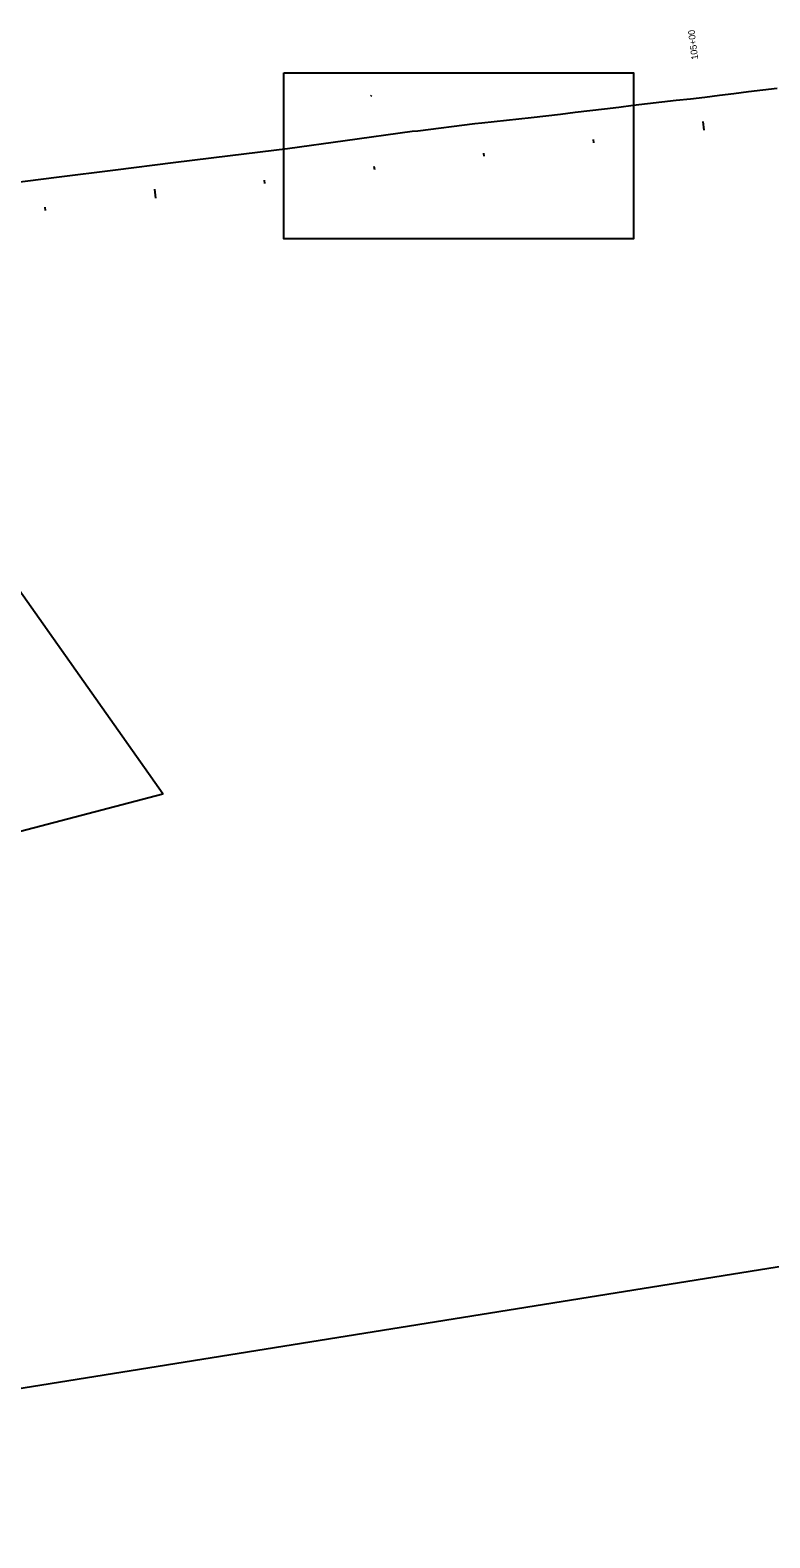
# Model space of a CAD drawing. Extents: x 1568908 to 1572777, y 730965 to 733090.
# Drawn here: x 1570174 to 1570843, y 730965 to 732330 of the extents above; entities that cross this region are included whole.
import ezdxf

# ---------------------------------------------------------------- set-up
doc = ezdxf.new("R2010")
doc.units = 0
for name, color, linetype in [('R_Erosion', 7, 'Continuous'), ('R_Horz Alg Annot', 7, 'Continuous'), ('R_No Plot', 7, 'Continuous')]:
    doc.layers.add(name, color=color, linetype=linetype)

msp = doc.modelspace()

# ---------------------------------------------------------------- linework, layer by layer
at = {"layer": 'R_Erosion'}
msp.add_line((1570481.8, 732270.6), (1570482.3, 732271.4), dxfattribs=at)
at = {"layer": 'R_Horz Alg Annot'}
for points in [[(1570782.1, 732247.6), (1570783.1, 732239.7)], [(1570683.7, 732228.4), (1570683.4, 732231.4)], [(1570584.5, 732216.1), (1570584.1, 732219.1)], [(1570485.3, 732203.9), (1570484.9, 732206.8)], [(1570285.9, 732186.3), (1570286.9, 732178.3)], [(1570386, 732191.6), (1570385.6, 732194.6)], [(1570187.5, 732167), (1570187.2, 732170)]]:
    msp.add_lwpolyline(points, dxfattribs=at)
at = {"layer": 'R_No Plot'}
for p, q in [((1570575.9, 732245.5), (1570524.3, 732238.8)), ((1570575.9, 732245.5), (1570524.3, 732238.8)), ((1570575.9, 732245.5), (1570524.3, 732238.8)), ((1570575.9, 732245.5), (1570524.3, 732238.8)), ((1569320, 730964.9), (1572777.4, 731520)), ((1569320, 730964.9), (1572777.4, 731520)), ((1569320, 730964.9), (1572777.4, 731520)), ((1569320, 730964.9), (1572777.4, 731520))]:
    msp.add_line(p, q, dxfattribs=at)
msp.add_lwpolyline([(1570403.1, 732291.6), (1570719.4, 732291.6), (1570719.4, 732141.4), (1570403.1, 732141.4)], close=True, dxfattribs=at)
for points in [[(1570849.4, 732277.6), (1570836.5, 732276), (1570823.4, 732274.4), (1570810.3, 732272.7), (1570797.2, 732271.1), (1570784.1, 732269.5), (1570771.2, 732268), (1570758.2, 732266.6), (1570745.2, 732265.1), (1570732.3, 732263.6), (1570719.2, 732262), (1570706.2, 732260.4), (1570693.1, 732258.8), (1570680.1, 732257.2), (1570666.8, 732255.7), (1570653.5, 732254.1), (1570640.3, 732252.6), (1570627, 732251.1), (1570604.6, 732248.5), (1570582.2, 732246), (1570575.9, 732245.5)], [(1570849.4, 732277.6), (1570836.5, 732276), (1570823.4, 732274.4), (1570810.3, 732272.7), (1570797.2, 732271.1), (1570784.1, 732269.5), (1570771.2, 732268), (1570758.2, 732266.6), (1570745.2, 732265.1), (1570732.3, 732263.6), (1570719.2, 732262), (1570706.2, 732260.4), (1570693.1, 732258.8), (1570680.1, 732257.2), (1570666.8, 732255.7), (1570653.5, 732254.1), (1570640.3, 732252.6), (1570627, 732251.1), (1570604.6, 732248.5), (1570582.2, 732246), (1570575.9, 732245.5)], [(1570849.4, 732277.6), (1570836.5, 732276), (1570823.4, 732274.4), (1570810.3, 732272.7), (1570797.2, 732271.1), (1570784.1, 732269.5), (1570771.2, 732268), (1570758.2, 732266.6), (1570745.2, 732265.1), (1570732.3, 732263.6), (1570719.2, 732262), (1570706.2, 732260.4), (1570693.1, 732258.8), (1570680.1, 732257.2), (1570666.8, 732255.7), (1570653.5, 732254.1), (1570640.3, 732252.6), (1570627, 732251.1), (1570604.6, 732248.5), (1570582.2, 732246), (1570575.9, 732245.5)], [(1570849.4, 732277.6), (1570836.5, 732276), (1570823.4, 732274.4), (1570810.3, 732272.7), (1570797.2, 732271.1), (1570784.1, 732269.5), (1570771.2, 732268), (1570758.2, 732266.6), (1570745.2, 732265.1), (1570732.3, 732263.6), (1570719.2, 732262), (1570706.2, 732260.4), (1570693.1, 732258.8), (1570680.1, 732257.2), (1570666.8, 732255.7), (1570653.5, 732254.1), (1570640.3, 732252.6), (1570627, 732251.1), (1570604.6, 732248.5), (1570582.2, 732246), (1570575.9, 732245.5)], [(1570524.3, 732238.8), (1570519.3, 732238.6), (1570458.6, 732230.1), (1570406.5, 732222.9), (1570354.4, 732216.4), (1570302.8, 732210.2), (1570250.7, 732203.6), (1570197.5, 732196.8), (1570145.1, 732190.3)], [(1570524.3, 732238.8), (1570519.3, 732238.6), (1570458.6, 732230.1), (1570406.5, 732222.9), (1570354.4, 732216.4), (1570302.8, 732210.2), (1570250.7, 732203.6), (1570197.5, 732196.8), (1570145.1, 732190.3)], [(1570524.3, 732238.8), (1570519.3, 732238.6), (1570458.6, 732230.1), (1570406.5, 732222.9), (1570354.4, 732216.4), (1570302.8, 732210.2), (1570250.7, 732203.6), (1570197.5, 732196.8), (1570145.1, 732190.3)], [(1570524.3, 732238.8), (1570519.3, 732238.6), (1570458.6, 732230.1), (1570406.5, 732222.9), (1570354.4, 732216.4), (1570302.8, 732210.2), (1570250.7, 732203.6), (1570197.5, 732196.8), (1570145.1, 732190.3)], [(1569359.2, 732036.1), (1569366.1, 732004.1), (1569660.8, 731472.6), (1570293.5, 731638.6), (1569963.2, 732107), (1569954.7, 732130.2)]]:
    msp.add_lwpolyline(points, dxfattribs=at)

# ---------------------------------------------------------------- texts
at = {"layer": 'R_Horz Alg Annot'}
msp.add_text('105+00', height=6, rotation=97.05, dxfattribs=at).set_placement((1570778, 732304.1))

doc.saveas('drawing.dxf')
